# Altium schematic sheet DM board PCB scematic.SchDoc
size 386 x 246 mm
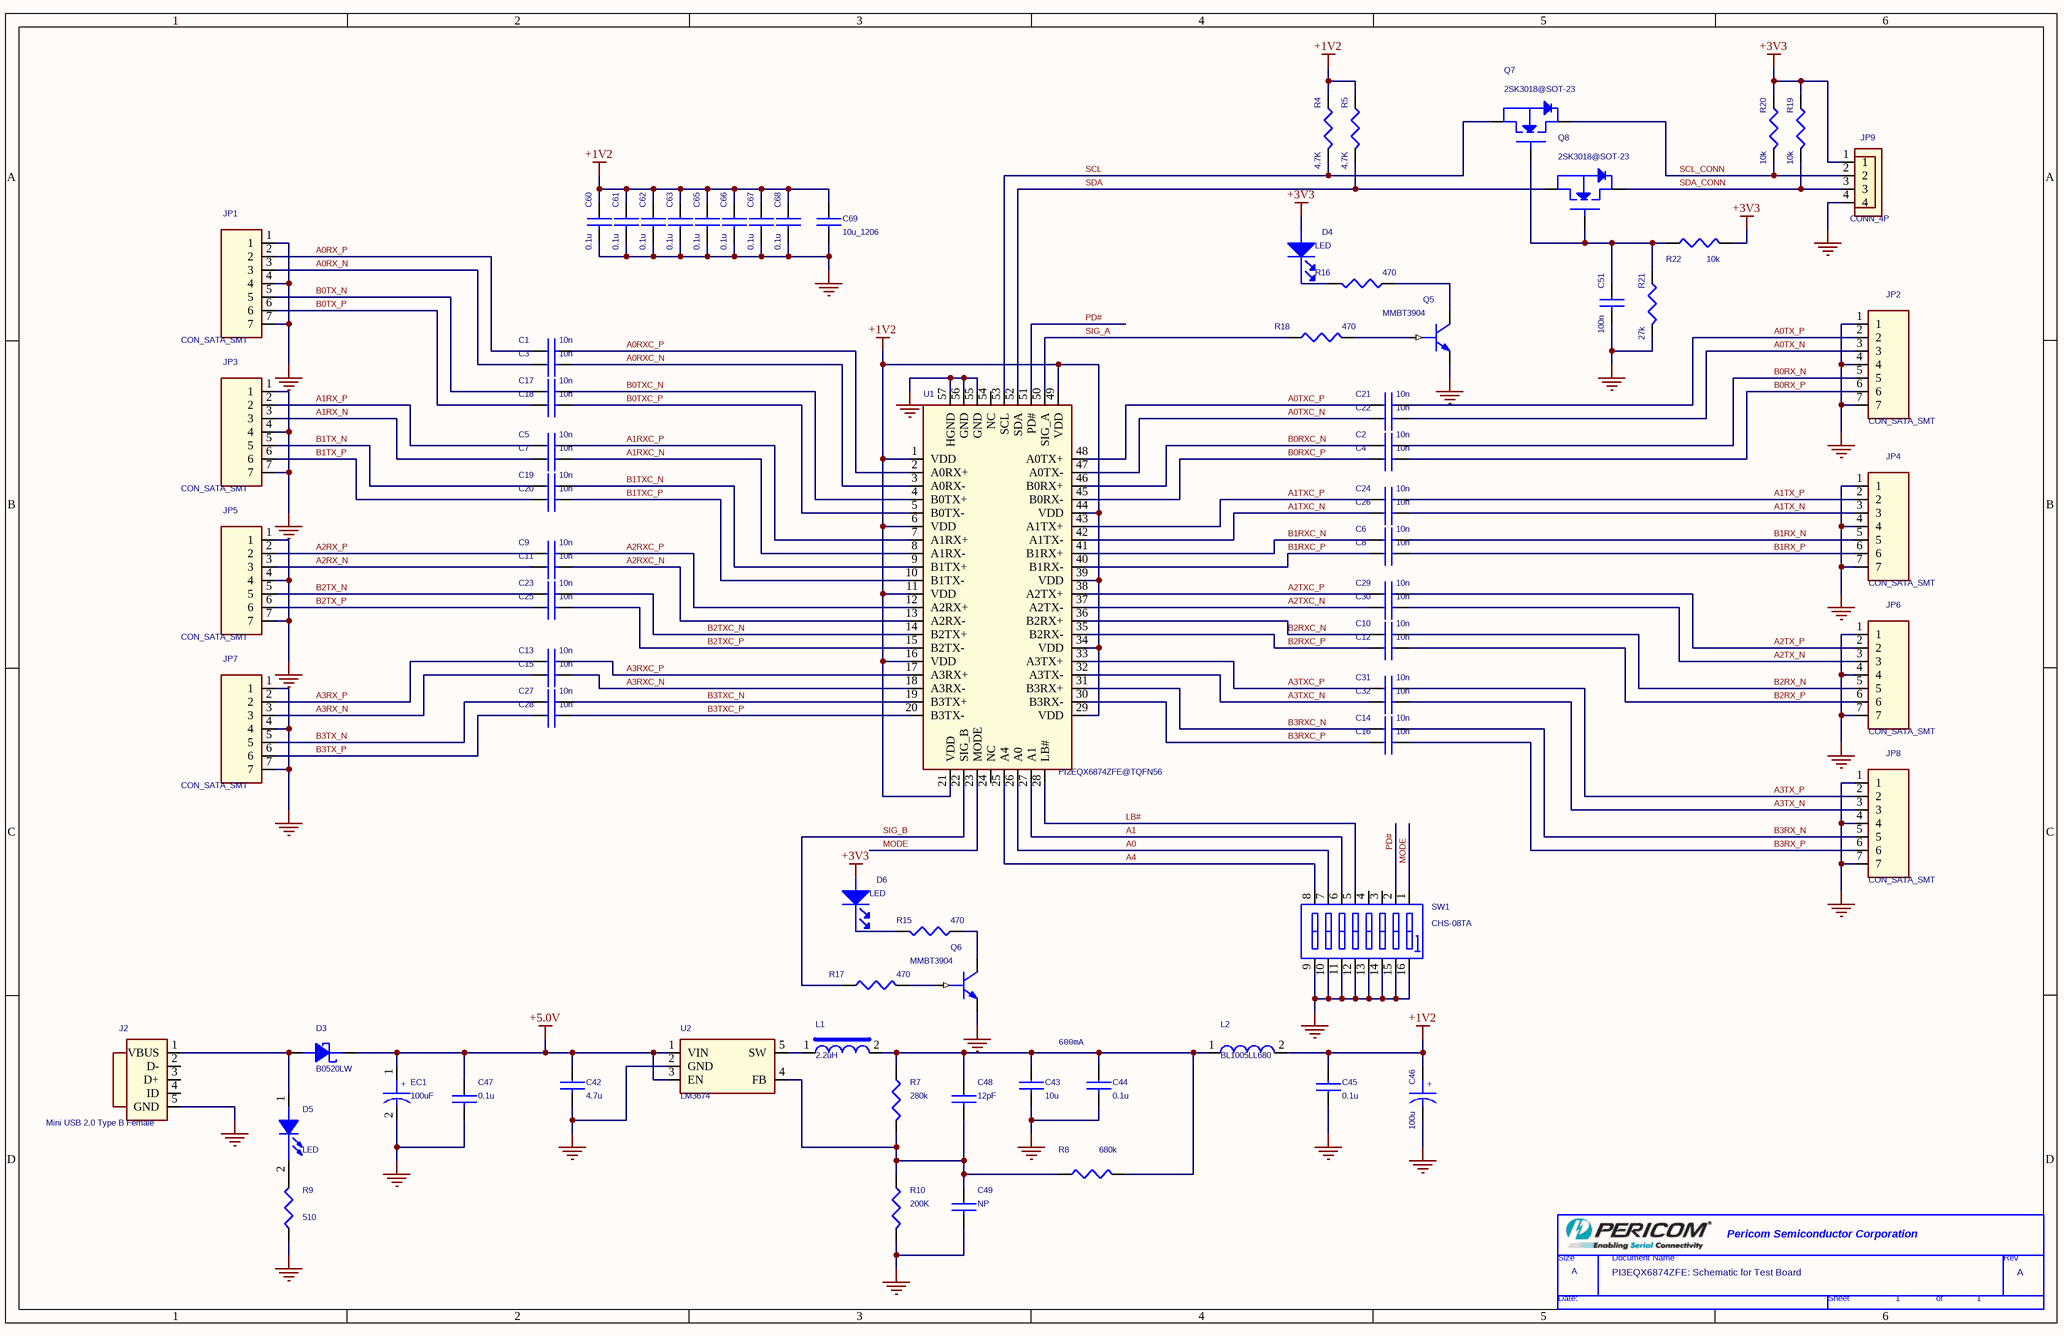
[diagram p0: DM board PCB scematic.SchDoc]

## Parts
*  Page Count: 1  Page Size: A  Doc: PI3EQX6874ZFE: Schematic for Test Board  (hidden comment: 0TitleBlock_PSC)  (graphical)
C1  10n  [CAP@CC_0402]
C2  10n  [CAP@CC_0402]
C3  10n  [CAP@CC_0402]
C4  10n  [CAP@CC_0402]
C5  10n  [CAP@CC_0402]
C6  10n  [CAP@CC_0402]
C7  10n  [CAP@CC_0402]
C8  10n  [CAP@CC_0402]
C9  10n  [CAP@CC_0402]
C10  10n  [CAP@CC_0402]
C11  10n  [CAP@CC_0402]
C12  10n  [CAP@CC_0402]
C13  10n  [CAP@CC_0402]
C14  10n  [CAP@CC_0402]
C15  10n  [CAP@CC_0402]
C16  10n  [CAP@CC_0402]
C17  10n  [CAP@CC_0402]
C18  10n  [CAP@CC_0402]
C19  10n  [CAP@CC_0402]
C20  10n  [CAP@CC_0402]
C21  10n  [CAP@CC_0402]
C22  10n  [CAP@CC_0402]
C23  10n  [CAP@CC_0402]
C24  10n  [CAP@CC_0402]
C25  10n  [CAP@CC_0402]
C26  10n  [CAP@CC_0402]
C27  10n  [CAP@CC_0402]
C28  10n  [CAP@CC_0402]
C29  10n  [CAP@CC_0402]
C30  10n  [CAP@CC_0402]
C31  10n  [CAP@CC_0402]
C32  10n  [CAP@CC_0402]
C42  4.7u  [CAP@CC_1206]
C43  10u  [CAP@CC_1206]
C44  0.1u  [CAP@CC_0402]
C45  0.1u  [CAP@CC_0402]
C46  100u  [CAP@CT_7343]
C47  0.1u  [CAP@CC_0402]
C48  12pF  [CAP@CC_0402]
C49  NP  [CAP@CC_0402]
C51  100n  [CAP@CC_0402]
C60  0.1u  [CAP@CC_0402]
C61  0.1u  [CAP@CC_0402]
C62  0.1u  [CAP@CC_0402]
C63  0.1u  [CAP@CC_0402]
C65  0.1u  [CAP@CC_0402]
C66  0.1u  [CAP@CC_0402]
C67  0.1u  [CAP@CC_0402]
C68  0.1u  [CAP@CC_0402]
C69  10u_1206  [CC_1206]
D3  B0520LW  [D@SOD-123]
D4  LED  [LED@LED_0805]
D5  LED  [LED0805]
D6  LED  [LED@LED_0805]
EC1  100uF  [CAP@CT_7343]
J2  Mini USB 2.0 Type B Female  [USB_B_MINI@USB_B_MINI]
JP1  CON_SATA_SMT  [CON_SATA_SMT]
JP2  CON_SATA_SMT  [CON_SATA_SMT]
JP3  CON_SATA_SMT  [CON_SATA_SMT]
JP4  CON_SATA_SMT  [CON_SATA_SMT]
JP5  CON_SATA_SMT  [CON_SATA_SMT]
JP6  CON_SATA_SMT  [CON_SATA_SMT]
JP7  CON_SATA_SMT  [CON_SATA_SMT]
JP8  CON_SATA_SMT  [CON_SATA_SMT]
JP9  CONN_4P  [I2C Host]
L1  2.2uH  [INDUCTORS-Power]
L2  BL1005LL680  [FB@LF0603]
Q5  MMBT3904  [Q(NPN)@SOT-23]
Q6  MMBT3904  [Q(NPN)@SOT-23]
Q7  2SK3018@SOT-23  [SOT-23]
Q8  2SK3018@SOT-23  [SOT-23]
R4  4.7K  [RES@R_0402]
R5  4.7K  [RES@R_0402]
R7  280k  [RES@R_0402]
R8  680k  [RES@R_0402]
R9  510  [RES@R_0402]
R10  200K  [RES@R_0402]
R15  470  [RES@R_0402]
R16  470  [RES@R_0402]
R17  470  [RES@R_0402]
R18  470  [RES@R_0402]
R19  10k  [RES@R_0402]
R20  10k  [RES@R_0402]
R21  27k  [RES@R_0402]
R22  10k  [RES@R_0402]
SW1  CHS-08TA  [CHS-08TA@CHS-08TA]
U1  PI2EQX6874ZFE@TQFN56  [TQFN56]
U2  LM3674  [SOT23-5]

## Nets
+1V2: C45.2 C46.1 C60.1 C61.1 C62.1 C63.1 C65.1 C66.1 C67.1 C68.1 C69.1 L2.2 R4.1 R5.1 U1.1(VDD) U1.6(VDD) U1.11(VDD) U1.16(VDD) U1.21(VDD) U1.29(VDD) U1.34(VDD) U1.39(VDD) U1.44(VDD) U1.49(VDD)
+3V3: D4.1(ANODE) D6.1(ANODE) JP9.1 R19.1 R20.1 R22.2
+5.0V: C42.1 C47.1 D3.2(CATHODE) EC1.1 U2.1(VIN) U2.3(EN)
GND: C42.2 C43.2 C44.2 C45.1 C46.2 C47.2 C49.2 C51.2 C60.2 C61.2 C62.2 C63.2 C65.2 C66.2 C67.2 C68.2 C69.2 EC1.2 J2.5(GND) JP1.1 JP1.4 JP1.7 JP2.1 JP2.4 JP2.7 JP3.1 JP3.4 JP3.7 JP4.1 JP4.4 JP4.7 JP5.1 JP5.4 JP5.7 JP6.1 JP6.4 JP6.7 JP7.1 JP7.4 JP7.7 JP8.1 JP8.4 JP8.7 JP9.4 Q5.E Q6.E R9.1 R10.2 R21.2 SW1.9(B8) SW1.10(B7) SW1.11(B6) SW1.12(B5) SW1.13(B4) SW1.14(B3) SW1.15(B2) SW1.16(B1) U1.55(GND) U1.56(GND) U1.57(HGND) U2.2(GND)
A0: SW1.7(A7) U1.26(A0)
A0RX_N: C3.1 JP1.3
A0RX_P: C1.1 JP1.2
A0RXC_N: C3.2 U1.3(A0RX-)
A0RXC_P: C1.2 U1.2(A0RX+)
A0TX_N: C22.2 JP2.3
A0TX_P: C21.2 JP2.2
A0TXC_N: C22.1 U1.47(A0TX-)
A0TXC_P: C21.1 U1.48(A0TX+)
A1: SW1.6(A6) U1.27(A1)
A1RX_N: C7.1 JP3.3
A1RX_P: C5.1 JP3.2
A1RXC_N: C7.2 U1.8(A1RX-)
A1RXC_P: C5.2 U1.7(A1RX+)
A1TX_N: C26.2 JP4.3
A1TX_P: C24.2 JP4.2
A1TXC_N: C26.1 U1.42(A1TX-)
A1TXC_P: C24.1 U1.43(A1TX+)
A2RX_N: C11.1 JP5.3
A2RX_P: C9.1 JP5.2
A2RXC_N: C11.2 U1.13(A2RX-)
A2RXC_P: C9.2 U1.12(A2RX+)
A2TX_N: C30.2 JP6.3
A2TX_P: C29.2 JP6.2
A2TXC_N: C30.1 U1.37(A2TX-)
A2TXC_P: C29.1 U1.38(A2TX+)
A3RX_N: C15.1 JP7.3
A3RX_P: C13.1 JP7.2
A3RXC_N: C15.2 U1.18(A3RX-)
A3RXC_P: C13.2 U1.17(A3RX+)
A3TX_N: C32.2 JP8.3
A3TX_P: C31.2 JP8.2
A3TXC_N: C32.1 U1.32(A3TX-)
A3TXC_P: C31.1 U1.33(A3TX+)
A4: SW1.8(A8) U1.25(A4)
B0RX_N: C2.2 JP2.5
B0RX_P: C4.2 JP2.6
B0RXC_N: C2.1 U1.46(B0RX+)
B0RXC_P: C4.1 U1.45(B0RX-)
B0TX_N: C17.1 JP1.5
B0TX_P: C18.1 JP1.6
B0TXC_N: C17.2 U1.4(B0TX+)
B0TXC_P: C18.2 U1.5(B0TX-)
B1RX_N: C6.2 JP4.5
B1RX_P: C8.2 JP4.6
B1RXC_N: C6.1 U1.41(B1RX+)
B1RXC_P: C8.1 U1.40(B1RX-)
B1TX_N: C19.1 JP3.5
B1TX_P: C20.1 JP3.6
B1TXC_N: C19.2 U1.9(B1TX+)
B1TXC_P: C20.2 U1.10(B1TX-)
B2RX_N: C10.2 JP6.5
B2RX_P: C12.2 JP6.6
B2RXC_N: C10.1 U1.36(B2RX+)
B2RXC_P: C12.1 U1.35(B2RX-)
B2TX_N: C23.1 JP5.5
B2TX_P: C25.1 JP5.6
B2TXC_N: C23.2 U1.14(B2TX+)
B2TXC_P: C25.2 U1.15(B2TX-)
B3RX_N: C14.2 JP8.5
B3RX_P: C16.2 JP8.6
B3RXC_N: C14.1 U1.31(B3RX+)
B3RXC_P: C16.1 U1.30(B3RX-)
B3TX_N: C27.1 JP7.5
B3TX_P: C28.1 JP7.6
B3TXC_N: C27.2 U1.19(B3TX+)
B3TXC_P: C28.2 U1.20(B3TX-)
LB#: SW1.5(A5) U1.28(LB#)
MODE: SW1.1(A1) U1.23(MODE)
PD#: SW1.2(A2) U1.51(PD#)
SCL: Q7.S R4.2 U1.53(SCL)
SCL_CONN: JP9.2 Q7.D R20.2
SDA: Q8.S R5.2 U1.52(SDA)
SDA_CONN: JP9.3 Q8.D R19.2
SIG_A: R18.1 U1.50(SIG_A)
SIG_B: R17.1 U1.22(SIG_B)
NetC43_1: C43.1 C44.1 C48.1 L1.2 L2.1 R7.1 R8.1
NetC48_2: C48.2 C49.1 R7.2 R8.2 R10.1 U2.4(FB)
NetC51_1: C51.1 Q7.G Q8.G R21.1 R22.1
NetD3_1: D3.1(ANODE) D5.1(ANODE) J2.1(VBUS)
NetD4_2: D4.2(CATHODE) R16.2
NetD5_2: D5.2(CATHODE) R9.2
NetD6_2: D6.2(CATHODE) R15.2
NetL1_1: L1.1 U2.5(SW)
NetQ5_B: Q5.B R18.2
NetQ5_C: Q5.C R16.1
NetQ6_B: Q6.B R17.2
NetQ6_C: Q6.C R15.1

Not connected (* = marked no-connect by the designer): J2 2(D-) 3(D+) 4(ID); SW1 3(A3) 4(A4); U1 24(NC) 54(NC)

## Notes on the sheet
- 600mA

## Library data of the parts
C1-C32 C51 C60-C63 C65-C68 = CHIP CAP0402_Dup1
C42 C43 = CHIP CAP1206
C44 C47-C49 = CHIP CAP0402
C45 = CHIP CAP_11
C46 = ECAP@CT_0
C69 = C_10u_1206
D3 = 1N5817M/CYL
D4 D6 = LED_3
D5 = LED@LD0805_0
EC1 = ECAP@CT_7343
J2 = USB 2_0.0 Mini B Female
JP1-JP8 = CON_SATA_SMT_Dup1
L1 = INDUCTOR@INDUCTOR1_9
L2 = FB _0603
Q5 Q6 = T NPN BEC_0
R4 R5 R19-R22 = CHIP RES0402_0_Dup1
R7 R8 R10 = CHIP RES0402_2
R9 = CHIP RES0402_0
R15-R18 = CHIP RES0402_1
U1 = PI2EQX6874ZFE@TQFN56_1
U2 = LM3674@SOT23-5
